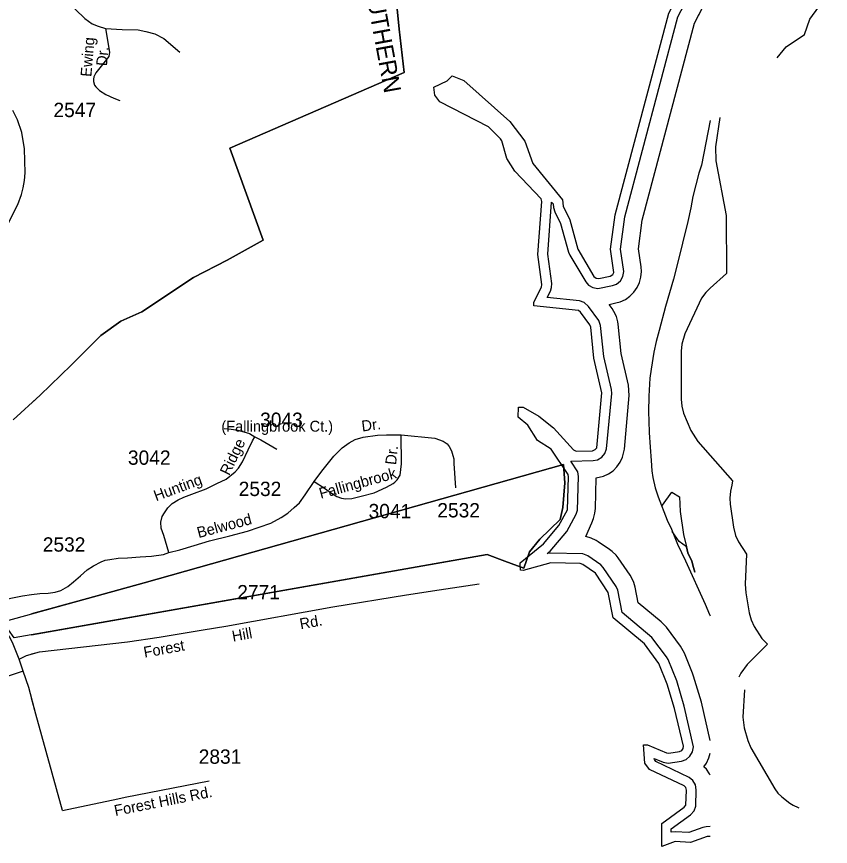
# Model space of a CAD drawing. Extents: x 1364363 to 1407445, y 538563 to 573342.
# Drawn here: x 1392969 to 1400067, y 538594 to 545834 of the extents above; entities that cross this region are included whole.
import ezdxf

# ---------------------------------------------------------------- set-up
doc = ezdxf.new("R2010")
doc.units = 0
for name, color, linetype in [('Exist Boundary Political City Limit New', 7, 'Continuous'), ('Exist Boundary Political City Limit New Hole', 7, 'Continuous'), ('Exist Boundary Political CountyLine', 7, 'Continuous'), ('Exist Hydrographic Bay Label', 7, 'Continuous'), ('Exist Hydrographic Buffer Line', 7, 'Continuous'), ('Exist Railroad Mainline Label', 7, 'Continuous'), ('Exist Road Primary NC Attributed', 7, 'Continuous'), ('Exist Road Secondary Type 51 Attributed', 7, 'Continuous'), ('Exist Road Secondary Type 51 Label', 7, 'Continuous'), ('Exist Road Secondary Type 51 Number Label', 7, 'Continuous')]:
    doc.layers.add(name, color=color, linetype=linetype)

msp = doc.modelspace()

# ---------------------------------------------------------------- linework, layer by layer
at = {"layer": 'Exist Boundary Political City Limit New'}
for points in [[(1397442.4, 541163.5), (1397393.9, 541022.2), (1397227, 541083.8), (1397072.1, 541140.9), (1392946.8, 540414.4), (1392848.4, 540552.2), (1393503.5, 540734.4), (1394081.5, 540895.2), (1397738.2, 541926.1), (1397751.5, 541765.6), (1397734, 541550.9), (1397709.5, 541446.2), (1397531.5, 541275.2), (1397442.4, 541163.5)], [(1397442.4, 541163.5), (1397531.5, 541275.2), (1397709.5, 541446.2), (1397734, 541550.9), (1397751.5, 541765.6), (1397738.2, 541926.1), (1394081.5, 540895.2), (1393503.5, 540734.4), (1393099.7, 540622.1)], [(1393099.7, 540441.3), (1397072.1, 541140.9), (1397227, 541083.8), (1397393.9, 541022.2), (1397442.4, 541163.5)]]:
    msp.add_lwpolyline(points, dxfattribs=at)
at = {"layer": 'Exist Boundary Political City Limit New Hole'}
for points in [[(1392939.9, 542316.6), (1393175.9, 542530.1), (1393445, 542792.4), (1393703.2, 543050.7), (1393879.4, 543176.6), (1394061.4, 543257.9), (1394513.4, 543558.9), (1394805, 543710.6), (1395120.5, 543882.9), (1394827.5, 544687.8), (1396348.4, 545345.4), (1396305.6, 545725.9), (1396183.1, 546956.9), (1395987.2, 546966.9), (1395957.4, 547169.6), (1395861, 547349.1), (1395771.4, 547475.4), (1395645.2, 547591.8), (1395462.6, 547701.4), (1395113.6, 547082.1), (1394128.9, 547058.8), (1393807.5, 546693.6)], [(1393807.5, 546693.6), (1394128.9, 547058.8), (1395113.6, 547082.1), (1395462.6, 547701.4), (1395645.2, 547591.8), (1395771.4, 547475.4), (1395861, 547349.1), (1395957.4, 547169.6), (1395987.2, 546966.9), (1396183.1, 546956.9), (1396305.6, 545725.9), (1396348.4, 545345.4), (1394827.5, 544687.8), (1395120.5, 543882.9), (1394805, 543710.6), (1394513.4, 543558.9), (1394061.4, 543257.9), (1393879.4, 543176.6), (1393703.2, 543050.7), (1393445, 542792.4), (1393175.9, 542530.1), (1393099.7, 542461.1)]]:
    msp.add_lwpolyline(points, dxfattribs=at)
at = {"layer": 'Exist Boundary Political CountyLine'}
msp.add_lwpolyline([(1399018.9, 544928.1), (1398942.1, 544539.1), (1398918.7, 544467.5), (1398868.4, 544264.7), (1398848.4, 544167), (1398822, 544047.5), (1398729.9, 543667.2), (1398697.4, 543543.8), (1398628.3, 543305), (1398571.9, 543096.1), (1398547.9, 542998.5), (1398528, 542906.9), (1398502.8, 542757.5), (1398493.2, 542679.7), (1398484.1, 542521.8), (1398481.1, 542385.8), (1398483.5, 542305.7), (1398487.5, 542205.6), (1398494.7, 542077.4), (1398502.4, 541961), (1398510.6, 541871), (1398517.2, 541812.8), (1398539.4, 541724.1), (1398563.8, 541643.6), (1398643.6, 541441.9), (1398680, 541361.1), (1398733.4, 541232), (1398802.3, 541086.5), (1398974.5, 540706.7), (1399012.7, 540617.9), (1399018.9, 540605.1)], dxfattribs=at)
at = {"layer": 'Exist Hydrographic Bay Label'}
msp.add_lwpolyline([(1399603.7, 545475), (1399681.6, 545571.9), (1399841.7, 545677), (1399886.7, 545810.7), (1400066.7, 546063)], dxfattribs=at)
at = {"layer": 'Exist Hydrographic Buffer Line'}
for points in [[(1398169.4, 543584.2), (1398178.1, 543602.9), (1398150.1, 543804.4), (1398189.2, 544104), (1398657.3, 545863.7), (1398829.2, 546197.6), (1398870.1, 546485.3), (1398892.2, 546501.6), (1399018.9, 546524.7)], [(1397634.7, 544216.2), (1397648.2, 544199.9), (1397651.7, 544167.6), (1397662.3, 544131.6), (1397714.2, 544030.2), (1397781.6, 543779.2), (1397793.1, 543752.6), (1397933.6, 543520.7), (1397958.1, 543492.2), (1397995.7, 543470.4), (1398039.2, 543462.9), (1398167.7, 543487.9), (1398201.9, 543501), (1398235.2, 543528.9), (1398257, 543566.8), (1398264.5, 543609.1), (1398236.1, 543805.2), (1398272.8, 544087.5), (1398737.4, 545832.8), (1398906.9, 546162.1), (1398917.3, 546195.5), (1398948.1, 546424.8), (1399018.9, 546437.8)], [(1397634.7, 544216.2), (1397648.2, 544199.9), (1397651.7, 544167.6), (1397662.3, 544131.6), (1397714.2, 544030.2), (1397781.6, 543779.2), (1397793.1, 543752.6), (1397933.6, 543520.7), (1397958.1, 543492.2), (1397995.7, 543470.4), (1398039.2, 543462.9), (1398167.7, 543487.9), (1398201.9, 543501), (1398235.2, 543528.9), (1398257, 543566.8), (1398264.5, 543609.1), (1398236.1, 543805.2), (1398272.8, 544087.5), (1398737.4, 545832.8), (1398906.9, 546162.1)], [(1398425, 544057.5), (1398882.5, 545776.8), (1399042.6, 546087.8)], [(1398425, 544057.5), (1398882.5, 545776.8), (1399018.9, 546041.8)], [(1398169.4, 543584.2), (1398178.1, 543602.9), (1398150.1, 543804.4), (1398189.2, 544104), (1398657.3, 545863.7)], [(1399018.9, 538681.1), (1398992.1, 538679.4), (1398845.8, 538627), (1398713.3, 538635.8), (1398597.8, 538594.2), (1398595.6, 538794.4), (1398791.2, 538936.6), (1398805.3, 538955.3), (1398810.7, 539086.1), (1398805.3, 539107.1), (1398790.7, 539121.7), (1398490.1, 539266.6), (1398446.9, 539319.6), (1398438.1, 539480.4), (1398471.3, 539479.8), (1398637.2, 539410.3), (1398658.9, 539407.7), (1398750.9, 539422.3), (1398770.5, 539431.1), (1398782.4, 539448.1), (1398784.1, 539468.7), (1398707.7, 539797.4), (1398644.1, 540011), (1398571.8, 540190), (1398444.8, 540362.2), (1398171.2, 540588.9), (1398127.9, 540808.8), (1398016.7, 540976.8), (1397907.2, 541054.8), (1397885.5, 541061.8), (1397627.4, 541067), (1397388.4, 541000.2), (1397363.9, 541003.1), (1397360.7, 541067.5), (1397565, 541234.1), (1397699.5, 541394.5), (1397773.1, 541531.2), (1397783.8, 541818.1), (1397778.3, 541839), (1397631, 542060.7), (1397511.5, 542136), (1397427.7, 542270.6), (1397344.1, 542339.4), (1397345.9, 542427), (1397387.7, 542426.2), (1397524.3, 542347.8), (1397650.4, 542247.2), (1397827.3, 542055.4), (1397849.7, 542043.2), (1397991.9, 542046.5), (1398016.5, 542055.8), (1398028.4, 542072.8), (1398073.6, 542551.4), (1398004.2, 542855.1), (1397976.5, 543125.6), (1397969, 543145.2), (1397887.9, 543255.2), (1397869.4, 543269), (1397480.7, 543311.8), (1397481.5, 543341.4), (1397547.4, 543473.2), (1397551.3, 543496.5), (1397516, 543759), (1397549.6, 544220.2), (1397544.4, 544243.1), (1397313.6, 544485.4), (1397245.6, 544596.8), (1397200.1, 544750.3), (1397189.7, 544767.5), (1397083.7, 544871.4), (1396661.5, 545089.3), (1396617, 545150.2), (1396607.4, 545219.4), (1396723.5, 545273.1), (1396769.3, 545317), (1396869.3, 545277.6), (1397270.2, 544918.9), (1397402.2, 544746.9), (1397471, 544551.2), (1397730.2, 544234.5), (1397736, 544180.7), (1397794.2, 544061.1), (1397863.1, 543804.4), (1398004.5, 543568.1), (1398025.1, 543551.2), (1398045.7, 543549.4), (1398147, 543570.7), (1398169.4, 543584.2)], [(1399102.9, 544954.2), (1399063.9, 544698.6), (1399066.3, 544576.5), (1399157.8, 544098.8), (1399159.3, 543592.5), (1399016.7, 543465.9), (1398979.9, 543428.1), (1398943.9, 543376.7), (1398798.1, 543065.1), (1398770.2, 542976.3), (1398764.7, 542913.8), (1398764.7, 542496.9), (1398770.2, 542434.4), (1398786.4, 542373.8), (1398849.1, 542224.3), (1398911.2, 542125.7), (1399214.3, 541783.8), (1399206.9, 541744.6), (1399194.2, 541694.1), (1399188.8, 541631.6), (1399192.5, 541580.3), (1399221.4, 541379.5), (1399239.3, 541307.7), (1399265.9, 541250.9), (1399334.2, 541144.9), (1399323, 540882.8), (1399327.9, 540806.4), (1399358, 540631.9), (1399374.4, 540569.8), (1399400.9, 540512.9), (1399469.9, 540408.8), (1399517.5, 540358.7), (1399340.9, 540180.5), (1399285, 540107.1), (1399267.9, 540070.6)], [(1397957.4, 543306.2), (1397919.4, 543340.3), (1397879.7, 543354.7), (1397597.6, 543383), (1397625.1, 543438), (1397635.6, 543469.5), (1397636.3, 543504.4), (1397601.6, 543761.6), (1397634.7, 544216.2)], [(1397957.4, 543306.2), (1397919.4, 543340.3), (1397879.7, 543354.7), (1397597.6, 543383), (1397625.1, 543438), (1397635.6, 543469.5), (1397636.3, 543504.4), (1397601.6, 543761.6), (1397634.7, 544216.2)], [(1399018.9, 539517.1), (1398941.5, 539851.8), (1398874, 540079.6), (1398865.2, 540104.7), (1398794.2, 540280.1), (1398759, 540342.6), (1398637, 540505.9), (1398590.7, 540554.5), (1398390.1, 540719.6), (1398363.4, 540855.1), (1398351.9, 540896.8), (1398331.3, 540941.1), (1398319.6, 540959.4), (1398214.6, 541112.6), (1398198.2, 541134.2), (1398163.7, 541168.7), (1398141.6, 541185.4), (1398042.5, 541253), (1398024.7, 541264.3), (1397980.5, 541285), (1397933.4, 541297.6), (1397984.9, 541418.6), (1398000.8, 541454.2), (1398013.4, 541501.3), (1398017.6, 541543.7), (1398023.6, 541809.1), (1398086.4, 541823.3), (1398130.7, 541843.9), (1398170.7, 541872), (1398205.2, 541906.5), (1398233.2, 541946.5), (1398253.8, 541990.7), (1398266.5, 542037.9), (1398269.6, 542060.9), (1398312.6, 542529.5), (1398306.3, 542619.1), (1398241.4, 542895), (1398215.2, 543150.1), (1398212.4, 543170.2), (1398199.8, 543217.3), (1398179.2, 543261.5), (1398162.1, 543287.6), (1398135.8, 543323.2), (1398196.2, 543335.8), (1398234.5, 543346.7), (1398278.8, 543367.3), (1398318.7, 543395.4), (1398353.2, 543429.9), (1398381.2, 543469.8), (1398401.9, 543514.1), (1398414.5, 543561.2), (1398418.7, 543609.8), (1398415.6, 543651.2), (1398392.5, 543806.8), (1398425, 544057.5)], [(1397801.9, 541956.8), (1397997.6, 541960.4), (1398034.4, 541967.3), (1398072.3, 541989.2), (1398100.6, 542023), (1398115, 542062.3), (1398159.8, 542547.2), (1398157.5, 542580.3), (1398089.4, 542869.5), (1398061.9, 543139.4), (1398047.6, 543182.9), (1397957.4, 543306.2)], [(1397801.9, 541956.8), (1397997.6, 541960.4), (1398034.4, 541967.3), (1398072.3, 541989.2), (1398100.6, 542023), (1398115, 542062.3), (1398159.8, 542547.2), (1398157.5, 542580.3), (1398089.4, 542869.5), (1398061.9, 543139.4), (1398047.6, 543182.9), (1397957.4, 543306.2)], [(1399018.9, 538767.4), (1398983.4, 538765.3), (1398954, 538759), (1398833.1, 538714.2), (1398714.2, 538722.2), (1398677.6, 538717), (1398679.3, 538748.8), (1398845.8, 538869.7), (1398877.3, 538904.7), (1398892.4, 538946.2), (1398897, 539088.1), (1398890.1, 539130.3), (1398867.8, 539168.7), (1398836, 539195.5), (1398544.9, 539335.9), (1398531.5, 539352.4), (1398531, 539361.3), (1398608.2, 539329), (1398651.5, 539320.3), (1398768.3, 539337.7), (1398808, 539351.7), (1398842, 539380.3), (1398863.9, 539418.3), (1398871.9, 539462.8), (1398791.3, 539818.1), (1398726, 540037.7), (1398650.6, 540225), (1398637.7, 540248.1), (1398510.6, 540418.2), (1398249.9, 540635.7), (1398211.8, 540829.2), (1398199.3, 540862.5), (1398086, 541028.2), (1398065.6, 541050.6), (1397951.9, 541128.8), (1397908.2, 541146.6), (1397625.9, 541153.3), (1397597.8, 541149.6), (1397622.7, 541170), (1397768.6, 541342.6), (1397850.8, 541493.7), (1397862.5, 541527.8), (1397870.1, 541820.5), (1397862.8, 541863.6), (1397801.9, 541956.8)], [(1398595.1, 541563.7), (1398603.6, 541572.2), (1398683.5, 541686.4), (1398749.9, 541644.5), (1398756.9, 541517.6), (1398785.9, 541316.8), (1398812.9, 541209), (1398823.6, 541156.8), (1398859.2, 541083.8), (1398873.6, 541027.9), (1398884.4, 540986.2)], [(1398884.4, 540986.2), (1398873.6, 541027.9), (1398859.2, 541083.8), (1398823.6, 541156.8), (1398812.9, 541209), (1398748.5, 541253.5), (1398688, 541341.7)], [(1399318.2, 539961.3), (1399304.2, 539720.6), (1399314.5, 539627.6), (1399345.4, 539518.7), (1399373.3, 539453.4), (1399582.3, 539097.9), (1399609.1, 539059.9), (1399643.7, 539025.4), (1399712.8, 538972.7), (1399741.7, 538953.5), (1399785.9, 538932.9), (1399792.3, 538931.1)], [(1399018.9, 539214.8), (1399013.2, 539227.1), (1398985.2, 539267.1), (1398963.8, 539288.4), (1398987.2, 539321.8), (1399007.8, 539366), (1399018.9, 539407.4)]]:
    msp.add_lwpolyline(points, dxfattribs=at)
at = {"layer": 'Exist Road Primary NC Attributed'}
msp.add_line((1393025.9, 540124.2), (1392991.7, 540228.7), dxfattribs=at)
for points in [[(1392899.1, 544036.2), (1392978.5, 544194.7), (1393012.3, 544282), (1393027.5, 544341.7), (1393038.8, 544405.5), (1393043.6, 544471.6), (1393042.4, 544575.6), (1393038.5, 544681.7), (1393015.4, 544824.2), (1392977.8, 544933), (1392935.4, 545013.9)], [(1392991.7, 540228.7), (1392934.8, 540373.9), (1392905.8, 540422.5), (1392827.9, 540532.1)], [(1393368.5, 538908.1), (1393137.9, 539747.3), (1393074.5, 539980.7), (1393025.9, 540124.2)], [(1393368.5, 538908.1), (1393137.9, 539747.3), (1393099.7, 539888)]]:
    msp.add_lwpolyline(points, dxfattribs=at)
at = {"layer": 'Exist Road Secondary Type 51 Attributed'}
msp.add_line((1393368.5, 538908.1), (1393852.7, 539010.2), dxfattribs=at)
msp.add_line((1393368.5, 538908.1), (1393852.7, 539010.2), dxfattribs=at)
for points in [[(1393147.2, 546287.1), (1393167.1, 546249.5), (1393243.3, 546155.8), (1393331.9, 546068.1), (1393484, 545896.7), (1393565.3, 545816.6), (1393628, 545772.6), (1393680, 545749.9), (1393744.4, 545729.7)], [(1393147.2, 546287.1), (1393167.1, 546249.5), (1393243.3, 546155.8), (1393331.9, 546068.1), (1393484, 545896.7), (1393565.3, 545816.6), (1393628, 545772.6), (1393680, 545749.9), (1393744.4, 545729.7)], [(1393744.4, 545729.7), (1393756.1, 545663.2), (1393770.7, 545573.8), (1393778.7, 545523.1), (1393773.4, 545485.8), (1393741.4, 545445.1), (1393660, 545342.4), (1393642.7, 545309), (1393638.7, 545287.7), (1393638.7, 545269), (1393649.4, 545237), (1393660, 545222.3), (1393693.4, 545188.9), (1393748.1, 545155.6), (1393817.4, 545123.6), (1393870.8, 545103.6)], [(1393744.4, 545729.7), (1393756.1, 545663.2), (1393770.7, 545573.8), (1393778.7, 545523.1), (1393773.4, 545485.8), (1393741.4, 545445.1), (1393660, 545342.4), (1393642.7, 545309), (1393638.7, 545287.7), (1393638.7, 545269), (1393649.4, 545237), (1393660, 545222.3), (1393693.4, 545188.9), (1393748.1, 545155.6), (1393817.4, 545123.6), (1393870.8, 545103.6)], [(1393744.4, 545729.7), (1393890.2, 545721.3), (1394029.5, 545717.5), (1394097.5, 545703.5), (1394174.3, 545682.6), (1394254.5, 545644.2), (1394394.1, 545525.5)], [(1393744.4, 545729.7), (1393890.2, 545721.3), (1394029.5, 545717.5), (1394097.5, 545703.5), (1394174.3, 545682.6), (1394254.5, 545644.2), (1394394.1, 545525.5)], [(1394780.1, 542240.8), (1394841.6, 542234.1), (1394897.7, 542224.9), (1394949.6, 542210.3), (1395000.2, 542197), (1395048, 542169.2)], [(1394780.1, 542240.8), (1394841.6, 542234.1), (1394897.7, 542224.9), (1394949.6, 542210.3), (1395000.2, 542197), (1395048, 542169.2)], [(1394297, 541158.6), (1394253.2, 541305.8), (1394231.4, 541370.8), (1394227.3, 541422.5), (1394238.2, 541471.6), (1394260.1, 541504.7), (1394287.4, 541547.2), (1394326.3, 541585.6), (1394376.9, 541617.5), (1394428.8, 541642.7), (1394496.5, 541667.9), (1394622.3, 541713), (1394715.9, 541759.4), (1394796.5, 541799.2), (1394875.8, 541862.8), (1394904.5, 541894.6), (1394938.7, 541950.3), (1394989.2, 542055.1), (1395027.5, 542133.3), (1395048, 542169.2)], [(1394297, 541158.6), (1394253.2, 541305.8), (1394231.4, 541370.8), (1394227.3, 541422.5), (1394238.2, 541471.6), (1394260.1, 541504.7), (1394287.4, 541547.2), (1394326.3, 541585.6), (1394376.9, 541617.5), (1394428.8, 541642.7), (1394496.5, 541667.9), (1394622.3, 541713), (1394715.9, 541759.4), (1394796.5, 541799.2), (1394875.8, 541862.8), (1394904.5, 541894.6), (1394938.7, 541950.3), (1394989.2, 542055.1), (1395027.5, 542133.3), (1395048, 542169.2)], [(1395048, 542169.2), (1395099.9, 542141.3), (1395238, 542060.4)], [(1395048, 542169.2), (1395099.9, 542141.3), (1395238, 542060.4)], [(1395564.6, 541779.3), (1395631.6, 541866.8), (1395736.9, 541999.4), (1395809.3, 542071), (1395869.4, 542116.1), (1395921.4, 542144), (1395991.1, 542165.2), (1396115.4, 542181.1), (1396194, 542185.1), (1396323.9, 542185.1)], [(1395564.6, 541779.3), (1395631.6, 541866.8), (1395736.9, 541999.4), (1395809.3, 542071), (1395869.4, 542116.1), (1395921.4, 542144), (1395991.1, 542165.2), (1396115.4, 542181.1), (1396194, 542185.1), (1396323.9, 542185.1)], [(1396086.7, 541679.8), (1396196.4, 541728.4), (1396254.2, 541762), (1396269.2, 541772.6), (1396289.7, 541791.2), (1396314.3, 541833.6), (1396325.3, 541931.8), (1396323.9, 542185.1)], [(1396086.7, 541679.8), (1396196.4, 541728.4), (1396254.2, 541762), (1396269.2, 541772.6), (1396289.7, 541791.2), (1396314.3, 541833.6), (1396325.3, 541931.8), (1396323.9, 542185.1)], [(1396323.9, 542185.1), (1396616.3, 542157.3), (1396688.1, 542130.4), (1396723, 542106.8), (1396741.4, 542083.1), (1396761.3, 542045.8), (1396773.9, 542004.4), (1396781.8, 541975.5), (1396783.1, 541935.7), (1396797.1, 541723.3)], [(1396323.9, 542185.1), (1396616.3, 542157.3), (1396688.1, 542130.4), (1396723, 542106.8), (1396741.4, 542083.1), (1396761.3, 542045.8), (1396773.9, 542004.4), (1396781.8, 541975.5), (1396783.1, 541935.7), (1396797.1, 541723.3)], [(1394297, 541158.6), (1394392.4, 541183.2), (1394518.6, 541219.6), (1394650.7, 541260.1), (1394829.2, 541305.1), (1394982.1, 541345.5), (1395187.3, 541415.3), (1395277.7, 541464.7), (1395335.6, 541503), (1395388.9, 541550.2), (1395435.3, 541592.9), (1395485.4, 541662.6), (1395564.6, 541779.3)], [(1394297, 541158.6), (1394392.4, 541183.2), (1394518.6, 541219.6), (1394650.7, 541260.1), (1394829.2, 541305.1), (1394982.1, 541345.5), (1395187.3, 541415.3), (1395277.7, 541464.7), (1395335.6, 541503), (1395388.9, 541550.2), (1395435.3, 541592.9), (1395485.4, 541662.6), (1395564.6, 541779.3)], [(1395564.6, 541779.3), (1395653.5, 541720.9), (1395716.4, 541675.8), (1395761.5, 541646.6), (1395802.5, 541633.4), (1395838, 541628.1), (1395892.7, 541630.7), (1395975.4, 541649.3), (1396086.7, 541679.8)], [(1395564.6, 541779.3), (1395653.5, 541720.9), (1395716.4, 541675.8), (1395761.5, 541646.6), (1395802.5, 541633.4), (1395838, 541628.1), (1395892.7, 541630.7), (1395975.4, 541649.3), (1396086.7, 541679.8)], [(1392693, 540706.4), (1392788.7, 540731.6), (1392878.2, 540751.5), (1392949.3, 540766.1), (1393020.4, 540779.3), (1393099.7, 540791.3), (1393172.1, 540801.9), (1393245.9, 540804.5), (1393304.7, 540812.5), (1393355.3, 540825.8), (1393416.1, 540861.6), (1393466.6, 540904), (1393526.8, 540954.4), (1393585.6, 541006.1), (1393639.5, 541041.9), (1393706.5, 541077.7), (1393742, 541092.3), (1393783.1, 541098.9), (1393854.1, 541108.2), (1393937.5, 541112.2), (1394045.5, 541121.5), (1394145.2, 541126.8), (1394249.1, 541141.4), (1394297, 541158.6)], [(1393099.7, 540791.3), (1393172.1, 540801.9), (1393245.9, 540804.5), (1393304.7, 540812.5), (1393355.3, 540825.8), (1393416.1, 540861.6), (1393466.6, 540904), (1393526.8, 540954.4), (1393585.6, 541006.1), (1393639.5, 541041.9), (1393706.5, 541077.7), (1393742, 541092.3), (1393783.1, 541098.9), (1393854.1, 541108.2), (1393937.5, 541112.2), (1394045.5, 541121.5), (1394145.2, 541126.8), (1394249.1, 541141.4), (1394297, 541158.6)], [(1392991.7, 540228.7), (1393054.6, 540260.8), (1393168, 540292.6), (1393935.4, 540378.8), (1394212.9, 540419.9), (1394596.3, 540484.9), (1394793.8, 540515.4), (1395728, 540685.2), (1396369.7, 540789.9), (1396656, 540833.7), (1397004.5, 540884.1)], [(1393099.7, 540273.5), (1393168, 540292.6), (1393935.4, 540378.8), (1394212.9, 540419.9), (1394596.3, 540484.9), (1394793.8, 540515.4), (1395728, 540685.2), (1396369.7, 540789.9), (1396656, 540833.7), (1397004.5, 540884.1)], [(1393025.9, 540124.2), (1392497.6, 539946.5), (1392102.3, 539794.9)], [(1393852.7, 539010.2), (1393915, 539022.9), (1394648.6, 539167.7)], [(1393852.7, 539010.2), (1393915, 539022.9), (1394648.6, 539167.7)]]:
    msp.add_lwpolyline(points, dxfattribs=at)

# ---------------------------------------------------------------- texts
at = {"layer": 'Exist Railroad Mainline Label'}
msp.add_text('NORFOLK SOUTHERN', height=150, rotation=280.44752, dxfattribs=at).set_placement((1395787.3, 547273.5))
msp.add_text('NORFOLK SOUTHERN', height=150, rotation=280.44752, dxfattribs=at).set_placement((1395787.3, 547273.5))
at = {"layer": 'Exist Road Secondary Type 51 Label'}
for s, rotation, p in [('Ewing', 85.16489, (1393620.8, 545306.2)), ('Ewing', 85.16489, (1393620.8, 545306.2)), (' Dr.', 85.16489, (1393754, 545365)), (' Dr.', 85.16489, (1393754, 545365)), ('Dr.', 7.29125, (1395983.5, 542213.8)), ('Dr.', 7.29125, (1395983.5, 542213.8)), ('Ridge', 64.23348, (1394823.1, 541824.2)), ('Ridge', 64.23348, (1394823.1, 541824.2)), ('Dr.', 83.64241, (1396278, 541919.5)), ('Dr.', 83.64241, (1396278, 541919.5)), ('Fallingbrook', 15.31329, (1395622.2, 541626.6)), ('Fallingbrook', 15.31329, (1395622.2, 541626.6)), ('Hunting', 20.42432, (1394186, 541604.7)), ('Hunting', 20.42432, (1394186, 541604.7)), ('Belwood', 14.82012, (1394556.7, 541283.9)), ('Belwood', 14.82012, (1394556.7, 541283.9)), ('Forest            Hill            Rd.', 10.29878, (1394085.8, 540240.2)), ('Forest            Hill            Rd.', 10.29878, (1394085.8, 540240.2)), ('Forest Hills Rd.', 11.16553, (1393830.4, 538859.2)), ('Forest Hills Rd.', 11.16553, (1393830.4, 538859.2))]:
    msp.add_text(s, height=95, rotation=rotation, dxfattribs=at).set_placement(p)
msp.add_text('(Fallingbrook Ct.)', height=95, dxfattribs=at).set_placement((1394755, 542213))
msp.add_text('(Fallingbrook Ct.)', height=95, dxfattribs=at).set_placement((1394755, 542213))
at = {"layer": 'Exist Road Secondary Type 51 Number Label'}
for s, p in [('2547', (1393290.5, 544957.5)), ('2547', (1393290.5, 544957.5)), ('3043', (1395093, 542254.1)), ('3043', (1395093, 542254.1)), ('3042', (1393940, 541923.9)), ('3042', (1393940, 541923.9)), ('2532', (1394906.2, 541651.1)), ('2532', (1394906.2, 541651.1)), ('3041', (1396038.8, 541457.3)), ('3041', (1396038.8, 541457.3)), ('2532', (1396638.4, 541464.7)), ('2532', (1396638.4, 541464.7)), ('2532', (1393197.5, 541165.9)), ('2532', (1393197.5, 541165.9)), ('2771', (1394893.4, 540749.7)), ('2771', (1394893.4, 540749.7)), ('2831', (1394557.5, 539315.1)), ('2831', (1394557.5, 539315.1))]:
    msp.add_text(s, height=125, dxfattribs=at).set_placement(p)

doc.saveas('drawing.dxf')
